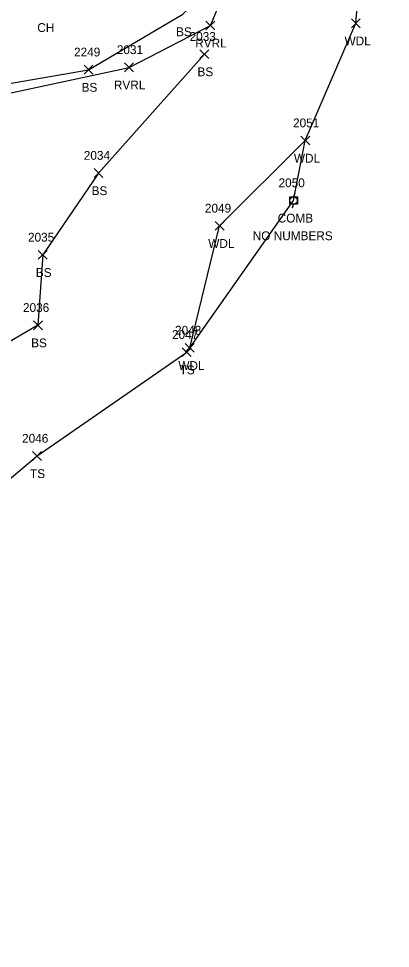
# Model space of a CAD drawing. Extents: x 1633660 to 1636532, y 388643 to 392631.
# Drawn here: x 1634772.8 to 1634857.2, y 388902.9 to 389113.6 of the extents above; entities that cross this region are included whole.
import ezdxf

# ---------------------------------------------------------------- set-up
doc = ezdxf.new("R2010")
doc.units = 0
for name, color, linetype in [('L_A', 7, 'Continuous'), ('L_I', 7, 'Continuous'), ('L_TIC', 7, 'Continuous'), ('LAWA', 7, 'Continuous'), ('LAWE', 7, 'Continuous'), ('LELB', 7, 'Continuous'), ('LSOGP', 7, 'Continuous'), ('U_A', 7, 'Continuous'), ('U_C', 7, 'Continuous'), ('U_I', 7, 'Continuous'), ('UP', 7, 'Continuous')]:
    doc.layers.add(name, color=color, linetype=linetype)

msp = doc.modelspace()

# ---------------------------------------------------------------- linework, layer by layer
at = {"layer": 'L_TIC'}
for points in [[(1634815.33, 389111.04), (1634817.33, 389113.04)], [(1634817.33, 389111.04), (1634815.33, 389113.04)], [(1634848.33, 389111.53), (1634850.33, 389113.53)], [(1634850.33, 389111.53), (1634848.33, 389113.53)], [(1634813.97, 389104.53), (1634815.97, 389106.53)], [(1634815.97, 389104.53), (1634813.97, 389106.53)], [(1634787.69, 389101.01), (1634789.69, 389103.01)], [(1634789.69, 389101.01), (1634787.69, 389103.01)], [(1634796.9, 389101.54), (1634798.9, 389103.54)], [(1634798.9, 389101.54), (1634796.9, 389103.54)], [(1634836.85, 389084.95), (1634838.85, 389086.95)], [(1634838.85, 389084.95), (1634836.85, 389086.95)], [(1634789.96, 389077.59), (1634791.96, 389079.59)], [(1634791.96, 389077.59), (1634789.96, 389079.59)], [(1634817.43, 389065.63), (1634819.43, 389067.63)], [(1634819.43, 389065.63), (1634817.43, 389067.63)], [(1634777.32, 389059.05), (1634779.32, 389061.05)], [(1634779.32, 389059.05), (1634777.32, 389061.05)], [(1634776.25, 389043.1), (1634778.25, 389045.1)], [(1634778.25, 389043.1), (1634776.25, 389045.1)], [(1634809.97, 389036.99), (1634811.97, 389038.99)], [(1634811.97, 389036.99), (1634809.97, 389038.99)], [(1634810.65, 389037.97), (1634812.65, 389039.97)], [(1634812.65, 389037.97), (1634810.65, 389039.97)], [(1634776.03, 389013.48), (1634778.03, 389015.48)], [(1634778.03, 389013.48), (1634776.03, 389015.48)]]:
    msp.add_lwpolyline(points, dxfattribs=at)
at = {"layer": 'LAWA'}
msp.add_lwpolyline([(1634811.65, 389038.97), (1634818.43, 389066.63), (1634837.85, 389085.95), (1634849.33, 389112.53), (1634851.42, 389137.05), (1634857.15, 389168.51), (1634851.26, 389192.25), (1634842.56, 389222.61), (1634839.17, 389244.57), (1634831.58, 389261.41), (1634825.76, 389253.02), (1634813.48, 389243.97), (1634799.9, 389233.03), (1634793.09, 389231.99)], dxfattribs=at)
at = {"layer": 'LAWE'}
msp.add_lwpolyline([(1634485.27, 388945.87), (1634504.2, 388941.24), (1634525.53, 388940.73), (1634548.51, 388932.94), (1634584.66, 388920), (1634598.75, 388914.41), (1634618.8, 388928.88), (1634638.3, 388944.91), (1634660.99, 388957.08), (1634677.58, 388983.24), (1634696.95, 389006.4), (1634707.36, 389033.31), (1634727.93, 389056.72), (1634749.89, 389078.7), (1634762.92, 389095.06), (1634797.9, 389102.54), (1634816.33, 389112.04), (1634824.18, 389130.77), (1634824.18, 389150.65), (1634818.45, 389174.95), (1634815.05, 389205.92), (1634802.11, 389220.82), (1634788.76, 389226.82)], dxfattribs=at)
at = {"layer": 'LELB'}
for points in [[(1634633.7, 388947.02), (1634652.59, 388956.59), (1634671.2, 388984.13), (1634685.4, 389000.21), (1634693.63, 389014.81), (1634704.34, 389035.4), (1634725.63, 389062.25), (1634746.9, 389081.24), (1634759.28, 389096.89), (1634788.69, 389102.01), (1634810.12, 389114.6), (1634818.92, 389123.64), (1634818.09, 389148.69), (1634815.05, 389173.41), (1634811.19, 389202.43), (1634801.32, 389217.95), (1634788.87, 389224.41)], [(1634814.97, 389105.53), (1634790.96, 389078.59), (1634778.32, 389060.05), (1634777.25, 389044.1), (1634736.53, 389020.26), (1634716.62, 389001.22), (1634695.3, 388977.45), (1634671.56, 388965.45)], [(1634609.99, 388906.9), (1634623.86, 388926.68), (1634649.49, 388937.05), (1634665.45, 388952.5), (1634695.16, 388960.07), (1634729.71, 388982.06), (1634750.63, 388992.22), (1634777.03, 389014.48), (1634810.97, 389037.99)]]:
    msp.add_lwpolyline(points, dxfattribs=at)
at = {"layer": 'LSOGP'}
msp.add_lwpolyline([(1634218.98, 388740.85), (1634254.67, 388740.24), (1634315.25, 388739.85), (1634380.93, 388763.62), (1634394.19, 388796.15), (1634428.1, 388811.92), (1634452.29, 388827.49), (1634483.59, 388839.11), (1634515.33, 388848.44), (1634546.28, 388863.72), (1634572.45, 388876.23), (1634604.94, 388890.27), (1634644.29, 388911.66), (1634697.95, 388942.99), (1634729.71, 388982.06), (1634750.63, 388992.22), (1634777.03, 389014.48), (1634810.97, 389037.99), (1634811.65, 389038.97), (1634835.21, 389072.38), (1634837.85, 389085.95), (1634849.33, 389112.53), (1634851.42, 389137.05)], dxfattribs=at)
at = {"layer": 'UP'}
for p, q in [((1634834.38, 389071.54), (1634834.38, 389073.21)), ((1634834.38, 389073.21), (1634836.05, 389073.21)), ((1634835.46, 389074.04), (1634835.21, 389073.21)), ((1634836.05, 389073.21), (1634836.05, 389071.54)), ((1634836.05, 389071.54), (1634834.38, 389071.54)), ((1634834.96, 389070.71), (1634835.21, 389071.54)), ((1634835.21, 389072.38), (1634835.21, 389072.38))]:
    msp.add_line(p, q, dxfattribs=at)
msp.add_circle((1634835.21, 389072.38), 0.833, dxfattribs=at)

# ---------------------------------------------------------------- texts
at = {"layer": 'L_A'}
for s, p in [('CH', (1634777.09, 389110.55)), ('BS', (1634808.56, 389109.6)), ('RVRL', (1634812.9, 389107.04)), ('WDL', (1634846.75, 389107.53)), ('BS', (1634813.41, 389100.53)), ('BS', (1634787.13, 389097.01)), ('RVRL', (1634794.46, 389097.54)), ('WDL', (1634835.27, 389080.95)), ('BS', (1634789.41, 389073.59)), ('WDL', (1634815.85, 389061.63)), ('BS', (1634776.76, 389055.05)), ('BS', (1634775.69, 389039.1)), ('WDL', (1634809.07, 389033.97)), ('TS', (1634809.38, 389032.99)), ('TS', (1634775.44, 389009.48))]:
    msp.add_text(s, height=2, dxfattribs=at).set_placement(p)
at = {"layer": 'L_I'}
for s, p in [('2033', (1634811.63, 389108.53)), ('2249', (1634785.42, 389105.01)), ('2031', (1634795.12, 389105.54)), ('2051', (1634835.08, 389088.95)), ('2034', (1634787.63, 389081.59)), ('2049', (1634815.09, 389069.63)), ('2035', (1634774.98, 389063.05)), ('2036', (1634773.85, 389047.1)), ('2048', (1634808.32, 389041.97)), ('2047', (1634807.63, 389040.99)), ('2046', (1634773.64, 389017.48))]:
    msp.add_text(s, height=2, dxfattribs=at).set_placement(p)
at = {"layer": 'U_A'}
msp.add_text('COMB', height=2, dxfattribs=at).set_placement((1634831.6, 389067.38))
at = {"layer": 'U_C'}
msp.add_text('NO NUMBERS', height=2, dxfattribs=at).set_placement((1634825.94, 389063.38))
at = {"layer": 'U_I'}
msp.add_text('2050', height=2, dxfattribs=at).set_placement((1634831.79, 389075.38))

doc.saveas('drawing.dxf')
